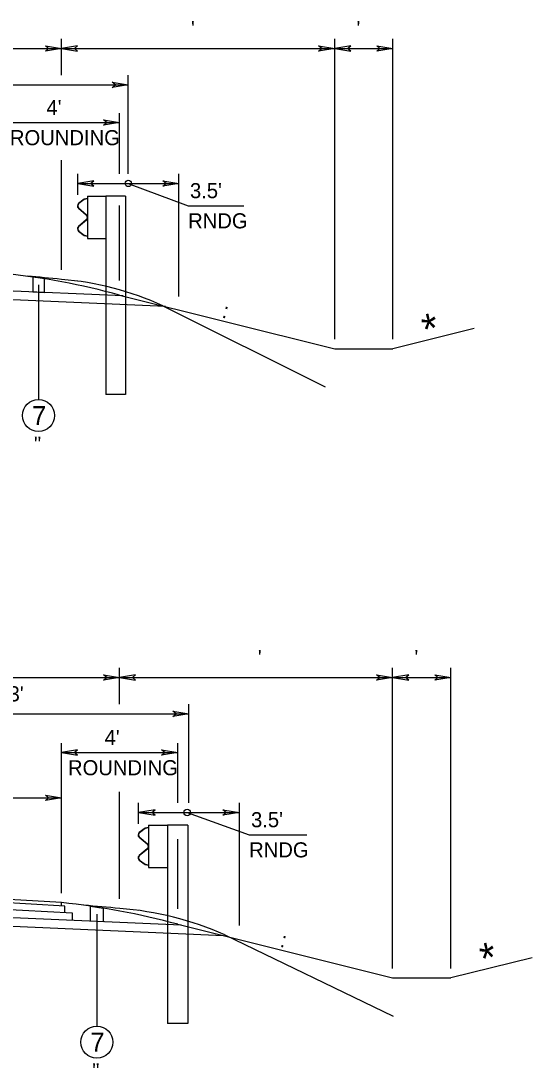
# Model space of a CAD drawing. Extents: x -592 to 1199, y -590 to 416.
# Drawn here: x 3.7 to 51.1, y 53.1 to 150.3 of the extents above; entities that cross this region are included whole.
import ezdxf

# ---------------------------------------------------------------- set-up
doc = ezdxf.new("R2010")
doc.units = 0
doc.layers.add('1', color=7, linetype='Continuous')
doc.layers.add('Des_ Drain_ Ftrs', color=7, linetype='Continuous')

msp = doc.modelspace()

# ---------------------------------------------------------------- linework, layer by layer
at = {"layer": '1'}
for p, q in [((-14.09, 147.702), (7.464, 147.702)), ((7.464, 145.216), (7.464, 148.582)), ((7.464, 147.702), (32.793, 147.702)), ((32.793, 120.711), (32.793, 148.582)), ((32.793, 147.702), (38.182, 147.702)), ((38.182, 120.711), (38.182, 148.582)), ((13.661, 136.06), (13.661, 145.216)), ((-14.089, 144.336), (13.661, 144.336)), ((12.85, 136.06), (12.85, 141.706)), ((2.074, 140.826), (12.85, 140.826)), ((7.464, 127.15), (7.464, 137.35)), ((8.969, 134.109), (8.969, 136.06)), ((18.353, 124.696), (18.353, 136.06)), ((8.969, 135.18), (18.353, 135.18)), ((13.661, 135.18), (19.218, 133.108)), ((9.567, 133.712), (9.05, 133.322)), ((9.579, 133.684), (9.068, 133.299)), ((9.881, 133.767), (9.567, 133.712)), ((9.881, 133.737), (9.579, 133.684)), ((9.881, 133.996), (9.881, 130.064)), ((9.881, 133.996), (11.566, 133.996)), ((11.566, 133.996), (11.566, 115.599)), ((13.392, 133.996), (11.566, 133.996)), ((12.85, 126.183), (12.85, 133.139)), ((13.392, 133.996), (13.392, 115.599)), ((9.035, 132.89), (9.766, 132.255)), ((9.054, 132.913), (9.785, 132.277)), ((19.218, 133.108), (24.373, 133.108)), ((9.766, 131.804), (9.035, 131.169)), ((9.785, 131.782), (9.054, 131.147)), ((9.852, 132.067), (9.852, 131.992)), ((9.881, 132.067), (9.881, 131.992)), ((9.05, 130.737), (9.567, 130.347)), ((9.068, 130.76), (9.579, 130.375)), ((9.567, 130.347), (9.881, 130.292)), ((9.579, 130.375), (9.881, 130.322)), ((9.881, 130.064), (11.566, 130.064)), ((13.189, 124.732), (-43.725, 127.217)), ((5.335, 125.774), (5.335, 115.123)), ((8.969, 126.049), (8.969, 126.049)), ((17.111, 123.752), (-12.443, 125.042)), ((12.85, 124.817), (32.793, 119.831)), ((16.853, 123.816), (31.904, 116.29)), ((45.717, 121.715), (38.182, 119.831)), ((45.717, 121.715), (38.182, 119.831)), ((32.793, 119.831), (38.182, 119.831)), ((13.392, 115.599), (11.566, 115.599)), ((12.849, 86.848), (12.849, 90.215)), ((38.168, 62.331), (38.168, 90.215)), ((43.556, 62.331), (43.556, 90.215)), ((-14.092, 89.335), (12.849, 89.335)), ((12.849, 89.335), (38.168, 89.335)), ((38.168, 89.335), (43.556, 89.335)), ((19.284, 77.692), (19.284, 86.848)), ((-14.086, 85.968), (19.284, 85.968)), ((7.46, 69.323), (7.46, 83.241)), ((18.236, 77.692), (18.236, 83.241)), ((7.46, 82.361), (18.236, 82.361)), ((12.849, 68.783), (12.849, 78.732)), ((-14.092, 78.177), (7.46, 78.177)), ((14.592, 75.741), (14.592, 77.692)), ((14.592, 76.812), (23.976, 76.812)), ((19.109, 76.812), (24.873, 74.741)), ((23.976, 66.328), (23.976, 77.692)), ((15.212, 75.344), (14.675, 74.955)), ((15.224, 75.316), (14.694, 74.931)), ((15.538, 75.4), (15.212, 75.344)), ((15.538, 75.37), (15.224, 75.316)), ((15.538, 75.628), (15.538, 71.696)), ((15.538, 75.628), (17.286, 75.628)), ((17.286, 75.628), (17.286, 57.231)), ((19.18, 75.628), (17.286, 75.628)), ((19.18, 75.628), (19.18, 57.231)), ((14.66, 74.523), (15.419, 73.887)), ((14.68, 74.545), (15.439, 73.91)), ((18.236, 67.871), (18.236, 74.333)), ((24.873, 74.741), (30.22, 74.741)), ((15.419, 73.437), (14.66, 72.802)), ((15.439, 73.414), (14.68, 72.779)), ((15.508, 73.7), (15.508, 73.624)), ((15.538, 73.7), (15.538, 73.624)), ((14.675, 72.369), (15.212, 71.98)), ((14.694, 72.393), (15.224, 72.008)), ((15.212, 71.98), (15.538, 71.924)), ((15.224, 72.008), (15.538, 71.954)), ((15.538, 71.696), (17.286, 71.696)), ((18.558, 66.353), (-43.728, 69.073)), ((7.459, 68.443), (-14.087, 69.695)), ((7.764, 68.125), (-13.852, 69.387)), ((8.491, 67.477), (-13.145, 68.547)), ((7.46, 68.143), (7.46, 68.443)), ((7.764, 67.513), (7.764, 68.125)), ((8.491, 66.793), (8.491, 67.477)), ((10.74, 67.386), (10.74, 56.979)), ((14.592, 67.681), (14.592, 67.681)), ((22.485, 65.372), (-12.445, 66.898)), ((18.236, 66.434), (38.168, 61.451)), ((22.595, 65.448), (38.208, 57.923)), ((51.091, 63.335), (43.556, 61.451)), ((38.168, 61.451), (43.556, 61.451)), ((19.18, 57.231), (17.286, 57.231))]:
    msp.add_line(p, q, dxfattribs=at)
for points in [[(5.89, 125.061), (5.89, 126.38), (4.796, 126.545), (4.796, 125.106)], [(10.167, 68.108), (11.313, 67.933), (11.313, 66.67), (10.167, 66.72)]]:
    msp.add_lwpolyline(points, close=True, dxfattribs=at)
for centre, radius in [((13.661, 135.18), 0.3), ((5.335, 113.638), 1.485), ((10.74, 55.494), 1.485)]:
    msp.add_circle(centre, radius, dxfattribs=at)
for centre, radius, start, end in [((9.217, 133.1), 0.278, 126.97989, 229.02099), ((9.217, 133.1), 0.249, 126.97989, 229.02099), ((9.603, 132.068), 0.249, 0, 49.03649), ((9.603, 132.068), 0.278, 0, 49.03649), ((9.217, 130.959), 0.278, 130.97902, 233.02011), ((9.603, 131.992), 0.249, 310.96352, 0), ((9.603, 131.992), 0.278, 310.96352, 0), ((9.217, 130.959), 0.249, 130.97902, 233.02011), ((-4.809, 59.991), 67.188, 74.76191, 84.12047), ((-3.354, 25.606), 101.244, 83.86333, 85.67746), ((5.346, 98.984), 27.368, 65.13739, 85.55132), ((0.574, 1.609), 67.188, 74.75976, 84.11833)]:
    msp.add_arc(centre, radius, start, end, dxfattribs=at)
msp.add_ellipse((19.109, 76.812), major_axis=(-0.311, 0), ratio=0.964041, dxfattribs=at)
for centre, major_axis, start_param, end_param in [((14.849, 74.733), (-0.288, 0), 5.35781, 7.138763), ((14.849, 74.733), (-0.258, 0), 5.35781, 7.138763), ((15.25, 73.7), (0.258, 0), 0, 0.855848), ((15.25, 73.7), (0.288, 0), 0, 0.855848), ((15.25, 73.624), (0.258, 0), 5.427337, 6.283185), ((15.25, 73.624), (0.288, 0), 5.427337, 6.283185), ((14.849, 72.591), (-0.288, 0), 5.427608, 7.208561), ((14.849, 72.591), (-0.258, 0), 5.427608, 7.208561), ((1.634, -32.762), (105.02, 0), 1.463691, 1.495354), ((10.659, 40.616), (28.389, 0), 1.136862, 1.493152)]:
    msp.add_ellipse(centre, major_axis=major_axis, ratio=0.964041, start_param=start_param, end_param=end_param, dxfattribs=at)
at = {"layer": 'Des_ Drain_ Ftrs'}
for points in [[(7.464, 147.702), (5.975, 147.454), (6.27, 147.702), (5.975, 147.951)], [(7.464, 147.702), (8.952, 147.454), (8.657, 147.702), (8.952, 147.951)], [(32.793, 147.702), (31.305, 147.454), (31.6, 147.702), (31.305, 147.951)], [(32.793, 147.702), (34.281, 147.454), (33.986, 147.702), (34.281, 147.951)], [(38.182, 147.702), (36.693, 147.454), (36.988, 147.702), (36.693, 147.951)], [(13.661, 144.336), (12.172, 144.087), (12.467, 144.336), (12.172, 144.584)], [(12.85, 140.826), (11.362, 140.577), (11.657, 140.826), (11.362, 141.074)], [(8.969, 135.18), (10.457, 134.931), (10.162, 135.18), (10.457, 135.428)], [(18.353, 135.18), (16.864, 134.931), (17.159, 135.18), (16.864, 135.428)], [(12.849, 89.335), (11.361, 89.086), (11.656, 89.335), (11.361, 89.583)], [(12.849, 89.335), (14.338, 89.086), (14.043, 89.335), (14.338, 89.583)], [(38.168, 89.335), (36.68, 89.086), (36.975, 89.335), (36.68, 89.583)], [(38.168, 89.335), (39.656, 89.086), (39.361, 89.335), (39.656, 89.583)], [(43.556, 89.335), (42.068, 89.086), (42.363, 89.335), (42.068, 89.583)], [(19.284, 85.968), (17.794, 85.72), (18.089, 85.968), (17.794, 86.216)], [(7.46, 82.361), (8.948, 82.112), (8.653, 82.361), (8.948, 82.609)], [(18.236, 82.361), (16.748, 82.112), (17.043, 82.361), (16.748, 82.609)], [(7.46, 78.177), (5.971, 77.929), (6.266, 78.177), (5.971, 78.426)], [(14.592, 76.812), (16.135, 76.564), (15.829, 76.812), (16.135, 77.06)], [(23.976, 76.812), (22.432, 76.564), (22.738, 76.812), (22.432, 77.06)]]:
    msp.add_lwpolyline(points, close=True, dxfattribs=at)

# ---------------------------------------------------------------- texts
at = {"layer": '1'}
for s, height, p in [("  '", 1.4, (18.432, 148.854)), (" '", 1.4, (34.292, 148.854)), ("4'", 1.4, (6.072, 141.525)), ('ROUNDING', 1.4, (2.683, 138.725)), ("3.5'", 1.4, (19.377, 133.808)), ('RNDG', 1.4, (19.208, 131.008)), ('7', 1.75, (4.745, 112.763)), (' "', 1.4, (4.392, 110.278)), ("  '", 1.4, (24.624, 90.486)), (" '", 1.4, (39.667, 90.486)), ("12.3'", 1.4, (-0.045, 87.119)), ("4'", 1.4, (11.457, 83.061)), ('ROUNDING', 1.4, (8.068, 80.261)), ("3.5'", 1.4, (25.038, 75.44)), ('RNDG', 1.4, (24.862, 72.64)), ('7', 1.75, (10.149, 54.618)), (' "', 1.4, (9.797, 52.134))]:
    msp.add_text(s, height=height, dxfattribs=at).set_placement(p)
for s, height, rotation, p in [(' : ', 1.4, 345.77179, (21.772, 122.876)), ('*', 2.8, 12.84793, (41.272, 120.185)), (' : ', 1.4, 345.77179, (27.152, 64.495)), ('*', 2.8, 12.84793, (46.646, 61.805))]:
    msp.add_text(s, height=height, rotation=rotation, dxfattribs=at).set_placement(p)

doc.saveas('drawing.dxf')
